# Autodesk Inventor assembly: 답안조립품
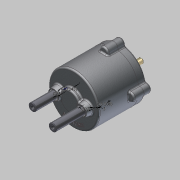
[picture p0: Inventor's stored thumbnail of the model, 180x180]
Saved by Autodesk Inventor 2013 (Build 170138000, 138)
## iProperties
Created: 2015-02
Part Number: 답안조립품
Document SubType Name: Assembly
Designer: Administrator
Mass: 1967.32 g
Surface Area: 1692.75 cm^2
Volume: 412.889 cm^3
Density: 4.76476 g/cm^3
Author: Administrator
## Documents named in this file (13)
- C:\Documents and Settings\Administrator\바탕 화면\350207V1022\답안조립품.iam
- C:\Documents and Settings\Administrator\바탕 화면\350207V1022\몸체.ipt
- C:\Documents and Settings\Administrator\바탕 화면\350207V1022\커버.ipt
- C:\Documents and Settings\Administrator\바탕 화면\350207V1022\오일실.ipt
- C:\Documents and Settings\Administrator\바탕 화면\350207V1022\M5x0.5x20.ipt
- C:\Documents and Settings\Administrator\바탕 화면\350207V1022\베어링 NA 4900.ipt
- C:\Documents and Settings\Administrator\바탕 화면\350207V1022\메인 축.ipt
- C:\Documents and Settings\Administrator\바탕 화면\350207V1022\멈춤링 22 x 1.2.ipt
- C:\Documents and Settings\Administrator\바탕 화면\350207V1022\멈춤링 10 x 1.ipt
- C:\Documents and Settings\Administrator\바탕 화면\350207V1022\판캠.ipt
- C:\Documents and Settings\Administrator\바탕 화면\350207V1022\슬라이드 축.ipt
- C:\Documents and Settings\Administrator\바탕 화면\350207V1022\11-가변스프링.ipt
- C:\Documents and Settings\Administrator\바탕 화면\350207V1022\12-가변스프링.ipt
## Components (6 placed, 3 different names)
1. 11-가변스프링:1
2. 12-가변스프링:1
3. M5x0.5x20:1
4. M5x0.5x20:2
5. M5x0.5x20:3
6. M5x0.5x20:4
